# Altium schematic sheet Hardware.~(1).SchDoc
size 431 x 279 mm; Date: Not shown in title block; ApprovedBy: Not shown in title block; CheckedBy: Not shown in title block; Author: Not shown in title block; CompanyName: Not shown in title block; DrawnBy: Salil Chellappan; Engineer: Not shown in title block; Organization: Not shown in title block; Address1: Not shown in title block; Address2: Not shown in title block; Address3: Not shown in title block; Address4: Not shown in title block; DocumentNumber: 1; Revision: Use project parameter SCH_Rev; SheetNumber: 3; SheetTotal: 3; PageSetup: Record=PageOptions|CenterHorizontal=True|CenterVertical=True|PrintScale=0.59|XCorrection=1.00|YCorrection=1.00|PrintKind=0|BorderSize=5000000|LeftOffset=0|BottomOffset=0|Orientation=2|PaperLength=1000|PaperWidth=1000|Scale=100|PaperSource=15|PrintQuality=600|MediaType=1|DitherType=10|PaperKind=Letter|PrintScaleMode=1
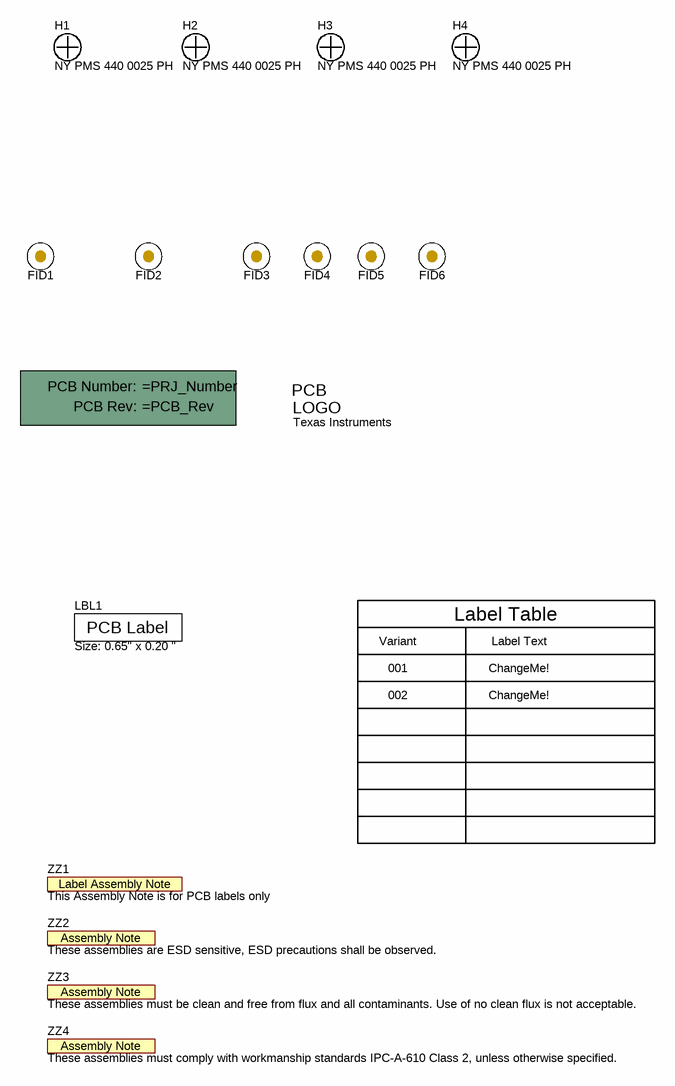
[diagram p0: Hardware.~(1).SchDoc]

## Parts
!PCB1  Printed Circuit Board  (value not drawn)  (mechanical)
FID1  Fiducial  [Fiducial10-20]  (value not drawn)
FID2  Fiducial  [Fiducial10-20]  (value not drawn)
FID3  Fiducial  [Fiducial10-20]  (value not drawn)
FID4  Fiducial  [Fiducial10-20]  (value not drawn)
FID5  Fiducial  [Fiducial10-20]  (value not drawn)
FID6  Fiducial  [Fiducial10-20]  (value not drawn)
H1  NY PMS 440 0025 PH  [NY PMS 440 0025 PH]
H2  NY PMS 440 0025 PH  [NY PMS 440 0025 PH]
H3  NY PMS 440 0025 PH  [NY PMS 440 0025 PH]
H4  NY PMS 440 0025 PH  [NY PMS 440 0025 PH]
LBL1  Size: 0.65" x 0.20 "  [Label_650x200]
Logo1  Texas Instruments  [TI_Stacked_Overlay_Small]  (no BOM)
ZZ1  This Assembly Note is for PCB labels only  [AssemblyNoteLabel]  (no BOM)
ZZ2  These assemblies are ESD sensitive, ESD precautions shall be observed.  [AssemblyNote]  (no BOM)
ZZ3  These assemblies must be clean and free from flux and all contaminants. Use of no clean flux is not acceptable.  [AssemblyNote]  (no BOM)
ZZ4  These assemblies must comply with workmanship standards IPC-A-610 Class 2, unless otherwise specified.  [AssemblyNote]  (no BOM)

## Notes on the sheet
- Label Table
- Variant
- 001
- Label Text
- ChangeMe!
- 002

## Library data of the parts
!PCB1 = PCB: Manufacturer: Any; SymbolCreator: a0412235
FID1-FID6 = Fiducial: Fiducial mark.  There is nothing to buy or mount.; SymbolCreator: codlsc
H1-H4 = NY PMS 440 0025 PH: Machine Screw, Round, #4-40 x 1/4, Nylon, Philips panhead; Manufacturer: B&F Fastener Supply; CompType: Hardware; SymbolCreator: codlsc; U/M: EA
LBL1 = THT-14-423-10: Thermal Transfer Printable Labels, 0.650" W x 0.200" H - 10,000 per roll; Manufacturer: Brady; SymbolCreator: a0412235; CompType: Label
Logo1 = TI_Logo: Texas Instrument Corporate Signature; SymbolCreator: codlsc
ZZ1 = AssemblyNoteLabel: SymbolCreator: a0412235
ZZ2-ZZ4 = AssemblyNote: SymbolCreator: codlsc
